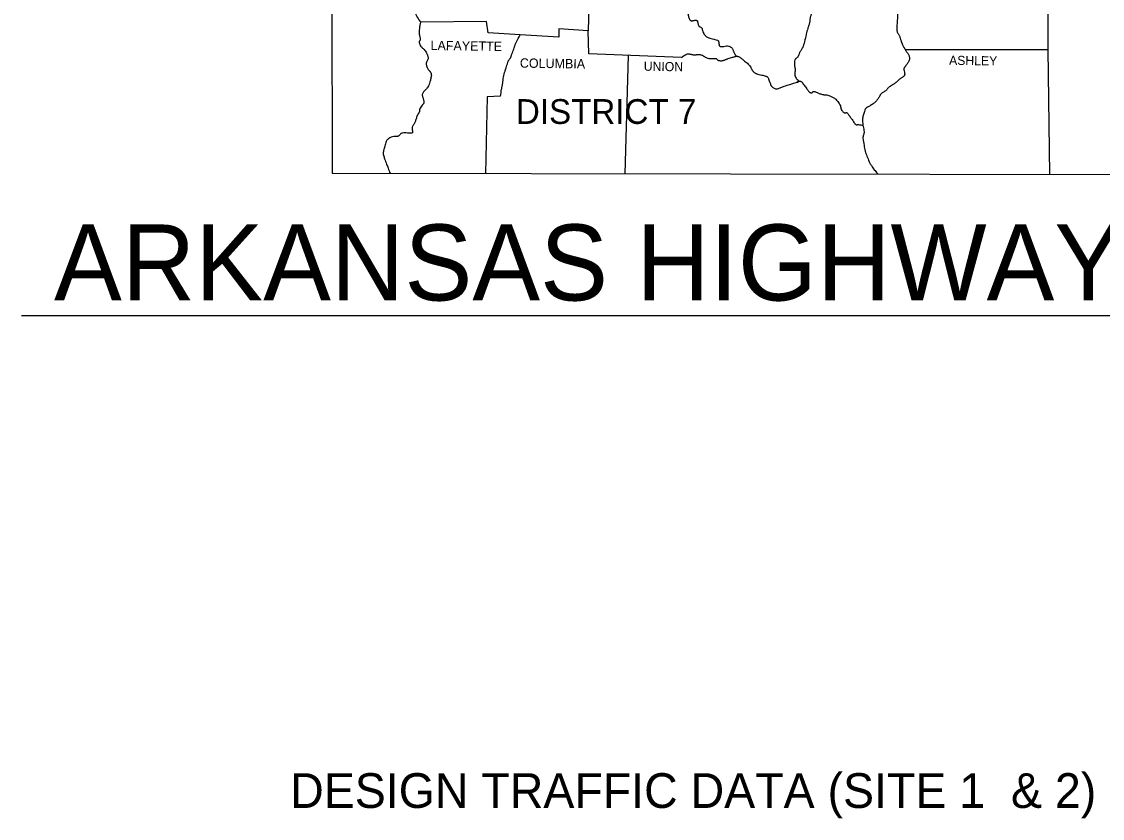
# Model space of a CAD drawing. Extents: x 982240 to 1103002, y 974866 to 1054902.
# Drawn here: x 1074271 to 1092173, y 1018146 to 1031353 of the extents above; entities that cross this region are included whole.
import ezdxf

# ---------------------------------------------------------------- set-up
doc = ezdxf.new("R2010")
doc.units = 0
for name, color, linetype in [('1', 7, 'Continuous'), ('Default', 7, 'Continuous'), ('R_Draft', 7, 'Continuous')]:
    doc.layers.add(name, color=color, linetype=linetype)

msp = doc.modelspace()

# ---------------------------------------------------------------- linework, layer by layer
at = {"layer": '1'}
for points in [[(1083703.9886225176, 1033012.2155825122), (1083657.1882101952, 1031197.8140686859), (1083171.2003717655, 1031230.2153271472), (1083167.6022496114, 1031097.0161299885), (1082527.014240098, 1031134.486481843)], [(1079409.2953796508, 1031752.2158338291), (1079416.4957613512, 1028839.815346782), (1092610.1656993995, 1028818.2158870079)], [(1082202.8269544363, 1030117.8162543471), (1081979.633050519, 1030103.4147755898), (1081955.1853419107, 1028835.6592383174)]]:
    msp.add_lwpolyline(points, dxfattribs=at)
for points in [[(1088790.6604119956, 1031590.2150583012), (1088779.8605290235, 1031478.6167001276), (1088776.262406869, 1031374.2149437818), (1088769.062025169, 1031273.4156258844), (1088767.087688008, 1031235.598910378), (1088767.3086761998, 1031216.6788174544), (1088769.062025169, 1031197.8140686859), (1088776.3027183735, 1031175.9372869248), (1088788.6335206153, 1031155.826065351), (1088801.9781133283, 1031136.0093056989), (1088812.2601779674, 1031115.0159096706), (1088837.460824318, 1031035.8146723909), (1088862.6587124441, 1030967.4152337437), (1088913.057246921, 1030877.4149561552), (1088924.268078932, 1030860.1013374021), (1088936.3278564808, 1030843.3429775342), (1088948.452087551, 1030826.5207473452), (1088959.856280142, 1030809.0155175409), (1088978.20725155, 1030760.7480627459), (1088979.756917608, 1030735.4033469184), (1088974.2556643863, 1030711.8145005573), (1088945.456895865, 1030661.416220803), (1088932.2416150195, 1030642.1728181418), (1088918.3002111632, 1030623.467603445), (1088904.4376407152, 1030604.8363081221), (1088891.4588600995, 1030585.8146636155), (1088885.4354231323, 1030552.9560086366), (1088893.1671679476, 1030515.3248719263), (1088899.144538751, 1030478.7389117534), (1088887.8579796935, 1030449.0157863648), (1088880.4175503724, 1030442.534947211), (1088872.4781238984, 1030436.8046951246), (1088855.7234263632, 1030426.7123790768), (1088838.8361810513, 1030416.9716919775), (1088823.058681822, 1030405.8154876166), (1088782.3237426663, 1030369.1105232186), (1088761.7694198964, 1030350.8515356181), (1088740.263256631, 1030333.8149896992), (1088693.462844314, 1030301.4164896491), (1088643.0629306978, 1030269.0152311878), (1088628.209558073, 1030256.1569261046), (1088615.1921282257, 1030241.1440818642), (1088602.6109354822, 1030225.6667126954), (1088589.0662740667, 1030211.4148328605), (1088569.875078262, 1030197.3160944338), (1088548.885977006, 1030185.1937644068), (1088528.1873537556, 1030172.6821338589), (1088509.8675919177, 1030157.4154938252), (1088493.7586899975, 1030136.2800200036), (1088480.4299675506, 1030112.9866138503), (1088467.4203282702, 1030089.4075782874), (1088452.268675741, 1030067.4152162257), (1088437.2962431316, 1030049.1207778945), (1088421.9703154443, 1030031.0722164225), (1088387.472136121, 1029999.0157776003), (1088333.4727212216, 1029963.0162182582), (1088314.6071453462, 1029951.5304510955), (1088295.4595497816, 1029940.6236635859), (1088267.060646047, 1029922.9799151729), (1088257.8749194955, 1029916.2148602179), (1088244.760818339, 1029901.5250716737), (1088236.335066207, 1029883.6092032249), (1088225.4738914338, 1029844.2157415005), (1088215.9339433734, 1029811.0186515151), (1088207.2961186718, 1029777.822225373), (1088201.4477083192, 1029744.5220684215), (1088200.2760033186, 1029711.0137859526), (1088204.660387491, 1029662.3356520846), (1088211.0745071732, 1029613.8141481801), (1088225.4738914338, 1029527.4163090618), (1088223.8529542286, 1029500.4159582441), (1088216.4710250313, 1029473.4156030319), (1088209.0908076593, 1029446.4152417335), (1088207.4750059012, 1029419.4148726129), (1088225.4738914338, 1029300.6157750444), (1088243.4741561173, 1029207.0158173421), (1088272.27430374, 1029124.2148999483), (1088311.8729552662, 1029030.6149422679), (1088335.361595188, 1028986.5048094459), (1088362.271489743, 1028944.2157239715), (1088407.4023034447, 1028882.752133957), (1088457.0853385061, 1028825.0149272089)], [(1082202.8269544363, 1030117.8162543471), (1082220.8258399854, 1030233.0142926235), (1082224.8831083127, 1030255.5947035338), (1082229.6028539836, 1030278.0579729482), (1082234.4338140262, 1030300.4998164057), (1082238.8247255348, 1030323.0159494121), (1082241.9532498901, 1030344.5411934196), (1082244.285017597, 1030366.1908963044), (1082246.586610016, 1030387.8529303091), (1082249.6246085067, 1030409.4151677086), (1082271.2243744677, 1030506.6148055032), (1082303.6226442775, 1030611.0151826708), (1082332.42141281, 1030697.4157801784), (1082336.1170022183, 1030705.6860105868), (1082340.8591860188, 1030713.4366187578), (1082352.1070546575, 1030728.063801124), (1082363.412454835, 1030742.6669926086), (1082368.2265529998, 1030750.3876122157), (1082372.0228225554, 1030758.6158585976), (1082378.443854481, 1030776.569236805), (1082384.6054780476, 1030794.620012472), (1082390.7755906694, 1030812.6684908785), (1082397.2220897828, 1030830.614977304), (1082429.6203596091, 1030917.0141956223), (1082437.343510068, 1030939.6851333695), (1082444.5642169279, 1030962.5647586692), (1082452.4125625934, 1030985.1691718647), (1082462.0186294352, 1031007.0144732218), (1082527.014240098, 1031134.486481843)]]:
    msp.add_spline(points, degree=3, dxfattribs=at)
at = {"layer": 'Default'}
for points in [[(1091267.398637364, 1033041.0157816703), (1091267.398637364, 1030888.2153756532), (1091296.1674780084, 1028820.367043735)], [(1081972.4312561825, 1031352.6146001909), (1080881.6582792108, 1031341.816443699)], [(1082527.014240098, 1031134.486481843), (1081997.6319360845, 1031165.4155686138), (1081972.4312561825, 1031352.6146001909)], [(1085201.550789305, 1030758.6158585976), (1083664.3885918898, 1030816.2134985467), (1083657.1882101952, 1031197.8140686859)], [(1088904.08492986, 1030891.8164349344), (1091267.398637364, 1030891.8164349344)], [(1084319.802163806, 1030791.6550784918), (1084262.6877868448, 1028831.8816080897)]]:
    msp.add_lwpolyline(points, dxfattribs=at)
for points in [[(1086089.3570193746, 1033160.2572362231), (1086087.0930818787, 1033048.3679949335), (1086084.5763867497, 1032992.4631158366), (1086082.5758888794, 1032964.5306763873), (1086079.9297788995, 1032936.6154044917), (1086069.0350314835, 1032880.494478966), (1086054.729132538, 1032825.0142879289), (1086045.1444954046, 1032773.9552819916), (1086039.0679090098, 1032748.7199653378), (1086034.8541442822, 1032736.3511370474), (1086032.3465934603, 1032730.2508408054), (1086029.5312444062, 1032724.2149700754), (1086018.6052799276, 1032707.5872354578), (1086004.951771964, 1032693.3169697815), (1085975.5318295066, 1032666.6145717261), (1085946.662048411, 1032637.8900108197), (1085917.9342924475, 1032609.0155525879), (1085863.934877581, 1032544.2157940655), (1085851.448016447, 1032524.9576722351), (1085840.6121293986, 1032504.617155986), (1085829.7378581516, 1032484.2756494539), (1085817.1358443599, 1032465.0145567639), (1085770.336811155, 1032414.6162770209), (1085709.1383937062, 1032364.2152388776), (1085647.9399762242, 1032328.2156795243), (1085579.5425561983, 1032295.814421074), (1085561.195891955, 1032289.9795412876), (1085542.1453718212, 1032286.3854944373), (1085522.8936486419, 1032283.0059659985), (1085503.9433753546, 1032277.814641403), (1085474.0414817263, 1032262.6909170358), (1085461.1371363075, 1032251.8515358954), (1085455.3108499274, 1032245.4117383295), (1085449.9453395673, 1032238.2154019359), (1085440.3468457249, 1032217.348654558), (1085437.283705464, 1032194.9831760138), (1085446.3444591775, 1032151.8161836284), (1085461.0037404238, 1032121.2008341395), (1085477.1031549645, 1032090.909350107), (1085493.122826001, 1032060.4708988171), (1085507.5428766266, 1032029.4146475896), (1085529.1412634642, 1031971.8142492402), (1085533.8913903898, 1031955.0859423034), (1085536.923410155, 1031937.8225876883), (1085537.8647968, 1031920.4552042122), (1085536.343024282, 1031903.4148106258), (1085511.1423779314, 1031863.8155711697), (1085453.5434617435, 1031831.4156919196), (1085385.1460416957, 1031791.8150732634), (1085323.9476242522, 1031755.8141347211), (1085309.4164316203, 1031744.2356686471), (1085297.7012587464, 1031729.5210616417), (1085288.309730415, 1031712.6533163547), (1085280.7494714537, 1031694.6154354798), (1085271.0732564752, 1031653.0734836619), (1085273.5504688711, 1031611.8158972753), (1085280.127384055, 1031587.4846301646), (1085287.8788003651, 1031563.2450397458), (1085295.6657430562, 1031538.9906238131), (1085302.349237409, 1031514.6148802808), (1085307.7414296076, 1031485.9254330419), (1085313.1477412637, 1031457.0158611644), (1085326.9032282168, 1031406.0561075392), (1085339.6173024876, 1031383.6989095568), (1085348.6555273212, 1031374.4791809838), (1085353.9976997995, 1031370.5063093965), (1085359.9467744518, 1031367.0142043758), (1085368.9107389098, 1031364.9493605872), (1085377.9097591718, 1031366.4270634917), (1085386.927074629, 1031369.0986016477), (1085395.9459246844, 1031370.615263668), (1085404.0450069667, 1031371.196860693), (1085412.1654191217, 1031372.366847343), (1085428.4280475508, 1031374.7056505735), (1085444.6494390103, 1031374.0989955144), (1085452.7183049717, 1031371.587159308), (1085456.737666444, 1031369.5859207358), (1085460.745222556, 1031367.0142043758), (1085466.2023319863, 1031358.6699789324), (1085467.944225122, 1031349.0158038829), (1085471.5437264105, 1031331.0146450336), (1085485.9431106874, 1031284.2160453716), (1085496.6047337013, 1031272.0990355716), (1085512.7640828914, 1031264.2394117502), (1085529.012799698, 1031256.4682948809), (1085539.9425255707, 1031244.6168059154), (1085542.464659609, 1031235.8855573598), (1085543.7222154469, 1031226.7115910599), (1085544.8896769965, 1031217.4896527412), (1085547.1415281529, 1031208.6144881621), (1085560.8473903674, 1031173.666687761), (1085579.5425561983, 1031140.2136703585), (1085590.9990375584, 1031125.6347414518), (1085603.6826554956, 1031112.7051174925), (1085633.5392128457, 1031093.4150706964), (1085673.1392434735, 1031079.0149711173), (1085755.9360477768, 1031053.8158312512), (1085799.1355796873, 1031043.0140325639), (1085805.265972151, 1031040.1450921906), (1085816.5658975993, 1031022.6435644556), (1085822.1280387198, 1030987.8404038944), (1085827.893708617, 1030954.5243081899), (1085834.6252748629, 1030943.3988337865), (1085845.934612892, 1030938.6150345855), (1085874.7287367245, 1030938.9673308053), (1085903.5321499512, 1030942.2160938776), (1085946.731681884, 1030949.4154540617), (1085983.1480196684, 1030947.6626796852), (1086001.0901162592, 1030941.6752567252), (1086009.9536803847, 1030937.120023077), (1086018.7299822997, 1030931.4156743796), (1086038.0069189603, 1030911.2204590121), (1086051.1296312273, 1030888.2153756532), (1086059.7452310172, 1030870.409527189), (1086067.2305704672, 1030852.2583363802), (1086074.7650077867, 1030834.0851958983), (1086083.5279010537, 1030816.2134985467), (1086102.52851999, 1030788.791992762), (1086112.724953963, 1030777.9937516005)], [(1087278.7002400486, 1032637.8157517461), (1087281.4197511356, 1032581.961295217), (1087284.8591124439, 1032526.1425324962), (1087293.0982452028, 1032414.6162770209), (1087299.4612541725, 1032387.1836858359), (1087310.5614141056, 1032360.5555213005), (1087321.0295570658, 1032333.9573754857), (1087324.3487571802, 1032320.4275571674), (1087325.496515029, 1032306.6148405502), (1087323.8233847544, 1032277.8893810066), (1087320.4667697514, 1032249.117829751), (1087316.9254014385, 1032220.2949295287), (1087314.6980111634, 1032191.4154230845), (1087311.0971307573, 1032079.8143065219), (1087311.0971307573, 1031979.0149886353), (1087311.0971307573, 1031881.8153508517), (1087311.0971307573, 1031781.0160329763), (1087318.2975124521, 1031709.0155350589), (1087323.643913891, 1031682.6927331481), (1087330.3689179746, 1031656.7232690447), (1087337.3580361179, 1031630.8001884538), (1087343.4967797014, 1031604.6165370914), (1087352.241520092, 1031556.0075339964), (1087354.5482273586, 1031531.6144112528), (1087354.298041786, 1031507.4155201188), (1087350.6389979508, 1031483.9216817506), (1087344.5315407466, 1031460.5763938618), (1087337.9067029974, 1031437.2506796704), (1087332.6955175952, 1031413.8155624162), (1087330.0225062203, 1031392.2812578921), (1087328.1671782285, 1031370.5216301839), (1087325.8767387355, 1031348.8088192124), (1087321.898392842, 1031327.4149649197), (1087315.4223878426, 1031305.5962119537), (1087307.7097639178, 1031284.1470273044), (1087299.8914175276, 1031262.7316620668), (1087293.0982452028, 1031241.0143674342), (1087267.8989779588, 1031143.8147296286), (1087239.0988303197, 1031017.8162718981), (1087227.9642930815, 1030976.0040740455), (1087221.357988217, 1030955.3897647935), (1087213.8995630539, 1030935.0153545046), (1087203.004972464, 1030912.4920665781), (1087189.805584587, 1030891.1481191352), (1087176.053552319, 1030870.1376399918), (1087163.501028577, 1030848.614756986), (1087154.706967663, 1030829.1822176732), (1087147.0760617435, 1030809.0674575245), (1087139.5580717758, 1030788.9263826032), (1087131.1027587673, 1030769.4148988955), (1087119.9919581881, 1030755.9525380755), (1087104.9990664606, 1030745.1235227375), (1087090.458042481, 1030733.8399359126), (1087084.7113430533, 1030727.0627041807), (1087080.702845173, 1030719.0138607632), (1087072.6862148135, 1030675.8338702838), (1087073.5038425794, 1030632.6160216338), (1087075.822927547, 1030612.8162357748), (1087079.0791519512, 1030593.0184359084), (1087082.2476923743, 1030573.2191195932), (1087084.3037255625, 1030553.4147843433), (1087083.599700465, 1030535.4516362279), (1087080.7780070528, 1030517.4437576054), (1087077.9194222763, 1030499.4216126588), (1087077.1047230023, 1030481.4156656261), (1087083.5707103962, 1030446.5703857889), (1087102.3026111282, 1030413.0162270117), (1087114.2948202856, 1030398.3160454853), (1087127.2178585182, 1030384.4152191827), (1087153.6203749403, 1030366.3540719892)], [(1079409.2953796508, 1031752.2158338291), (1079535.293094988, 1031806.2151728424), (1079589.292509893, 1031788.2140139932), (1079636.0915430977, 1031741.415414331), (1079690.0881997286, 1031741.415414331), (1079718.8897265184, 1031784.6143338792), (1079772.8863831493, 1031788.2140139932), (1079816.084535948, 1031784.6143338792), (1079862.8849482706, 1031813.4159122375), (1079902.483599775, 1031831.4156919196), (1079956.4830146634, 1031849.4154715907), (1079996.0830452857, 1031863.8155711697), (1080032.080816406, 1031903.4148106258), (1080096.8787351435, 1031935.8160690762), (1080172.476536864, 1031961.0152089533), (1080194.0763028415, 1031997.0161475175), (1080230.075453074, 1032011.4148679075), (1080302.0737535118, 1032007.8151878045), (1080348.8727866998, 1032029.4146475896), (1080388.4714382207, 1032011.4148679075), (1080424.4705884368, 1031986.2143488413), (1080431.6695910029, 1031892.6157703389), (1080460.469738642, 1031842.2161113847), (1080503.6692705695, 1031752.2158338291), (1080564.866308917, 1031705.4158549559), (1080622.4652250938, 1031658.6144969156), (1080644.0649910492, 1031629.8142977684), (1080705.264787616, 1031575.8163379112), (1080759.2628233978, 1031557.815179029), (1080784.462090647, 1031518.2159395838), (1080824.0607421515, 1031424.6146027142), (1080881.6582792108, 1031341.816443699)], [(1080881.6582792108, 1031341.816443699), (1080869.16222442, 1031295.5715398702), (1080864.1421879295, 1031265.9448360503), (1080860.0598923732, 1031237.4146873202), (1080856.4603911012, 1031154.6165283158), (1080859.1191552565, 1031130.0264634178), (1080864.8569138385, 1031105.5223518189), (1080870.8961324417, 1031081.2650742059), (1080874.45927665, 1031057.4155113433), (1080871.7854040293, 1031045.5602665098), (1080865.1192862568, 1031033.8682798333), (1080858.6234423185, 1031022.2499142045), (1080856.4603911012, 1031010.6155325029), (1080859.8341387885, 1030993.3485512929), (1080865.7983458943, 1030976.1464538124), (1080885.259159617, 1030942.2160938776), (1080898.4861488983, 1030926.8804918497), (1080912.496105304, 1030914.0441091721), (1080926.3870978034, 1030901.7935392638), (1080939.2571953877, 1030888.2153756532), (1080960.0711326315, 1030860.859052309), (1080978.8558468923, 1030830.614977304), (1080988.6136648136, 1030810.0164726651), (1080995.8224456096, 1030789.2249992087), (1081000.8480886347, 1030768.4282854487), (1081004.0564932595, 1030747.8140599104), (1081000.0120153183, 1030724.4040913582), (1080987.7998276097, 1030701.0022088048), (1080975.6160604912, 1030677.6066071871), (1080971.6568443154, 1030654.215481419), (1080976.2840854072, 1030629.7844752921), (1080983.976826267, 1030605.4431218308), (1081007.6559945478, 1030557.0144644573), (1081015.3010622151, 1030547.1667525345), (1081024.0242997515, 1030539.0305650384), (1081032.663296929, 1030530.8864373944), (1081040.055643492, 1030521.0149051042), (1081058.054529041, 1030463.4158859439), (1081054.5851127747, 1030435.5488259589), (1081048.8502574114, 1030407.6001492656), (1081032.8552617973, 1030351.8147693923), (1081000.4556128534, 1030269.0152311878), (1080993.0656228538, 1030257.4169023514), (1080984.6642717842, 1030246.7101034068), (1080965.9304227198, 1030226.9013991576), (1080946.4599383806, 1030207.4497263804), (1080928.4586915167, 1030186.2156929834), (1080906.858925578, 1030146.6164535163), (1080917.657429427, 1030092.6143561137), (1080922.85634906, 1030070.9497782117), (1080928.61462146, 1030049.263900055), (1080933.3943640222, 1030027.6534453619), (1080934.9366982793, 1030016.9067279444), (1080935.4118782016, 1030011.5532863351), (1080935.6576941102, 1030006.2151378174), (1080929.06104324, 1029992.9894681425), (1080923.1090814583, 1029987.0544296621), (1080917.657429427, 1029981.0159979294), (1080894.017931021, 1029950.5894248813), (1080870.8597753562, 1029919.815919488), (1080864.3077642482, 1029903.9990238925), (1080862.2108510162, 1029886.3117199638), (1080860.8385538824, 1029868.2766561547), (1080856.4603911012, 1029851.4164808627), (1080848.7946886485, 1029836.8733062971), (1080840.0547281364, 1029822.7403658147), (1080831.4176868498, 1029808.54538331), (1080824.0607421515, 1029793.8160825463), (1080814.40426392, 1029768.0222917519), (1080805.8783179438, 1029741.6545486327), (1080797.4437965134, 1029715.2678229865), (1080788.0615919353, 1029689.4170845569), (1080777.5779044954, 1029667.2887068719), (1080765.2834194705, 1029645.8068912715), (1080752.6786071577, 1029624.5296781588), (1080741.2639378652, 1029603.015107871), (1080738.949742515, 1029575.6754174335), (1080744.7285003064, 1029543.6132916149), (1080746.97488143, 1029516.9521644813), (1080743.1405152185, 1029508.8105485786), (1080734.0635561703, 1029505.8154700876), (1080662.0652557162, 1029505.8154700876), (1080579.2670722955, 1029505.8154700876), (1080558.525454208, 1029498.410675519), (1080540.881819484, 1029481.5692913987), (1080523.531360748, 1029463.3508170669), (1080503.6692705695, 1029451.8147518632), (1080486.9661136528, 1029449.6827573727), (1080469.68638789, 1029449.8905766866), (1080452.2984036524, 1029450.1605635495), (1080435.2704714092, 1029448.2150717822), (1080392.798001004, 1029436.7750452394), (1080352.4736671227, 1029415.8151925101), (1080335.2331943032, 1029401.2031360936), (1080320.9510237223, 1029384.9756305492), (1080302.0737535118, 1029347.4157538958), (1080284.0734888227, 1029271.8155758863), (1080278.6156161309, 1029253.8163023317), (1080272.5321265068, 1029235.8563274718), (1080262.475101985, 1029199.816457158), (1080260.720339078, 1029169.3134255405), (1080265.0992802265, 1029138.2353755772), (1080273.5657289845, 1029107.3474823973), (1080284.0734888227, 1029077.4149211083), (1080316.47451689, 1028991.0157028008), (1080341.6724050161, 1028922.6148849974), (1080373.9269056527, 1028838.2479288)], [(1085201.550789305, 1030758.6158585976), (1085259.1510845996, 1030798.2150980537), (1085313.1477412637, 1030819.8145578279), (1085340.03427056, 1030815.1307399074), (1085353.547070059, 1030811.7301533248), (1085367.1471561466, 1030809.0155175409), (1085424.7446932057, 1030801.8161573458), (1085437.3487096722, 1030802.392792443), (1085449.9485072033, 1030804.8880751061), (1085462.5463761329, 1030807.647238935), (1085475.1446068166, 1030809.0155175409), (1085539.9425255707, 1030798.2150980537), (1085554.401131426, 1030790.8694859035), (1085567.5720320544, 1030782.3500040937), (1085580.428033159, 1030773.6634442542), (1085593.941940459, 1030765.8165979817), (1085623.7130027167, 1030749.4891099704), (1085655.140357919, 1030740.6146997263), (1085716.3373962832, 1030740.6146997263), (1085770.336811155, 1030740.6146997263), (1085783.1218133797, 1030736.0392453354), (1085794.1004615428, 1030725.7136130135), (1085804.8970428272, 1030714.738899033), (1085817.1358443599, 1030708.2161996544), (1085838.3687433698, 1030705.2159836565), (1085860.4451941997, 1030704.4598541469), (1085882.466046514, 1030706.4814726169), (1085903.5321499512, 1030711.8145005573), (1085921.571055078, 1030718.7784393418), (1085939.4410952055, 1030726.3581411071), (1085957.3565825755, 1030733.8660723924), (1085975.5318295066, 1030740.6146997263), (1086047.5301299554, 1030762.2155386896), (1086071.7703347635, 1030769.4641795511), (1086096.728032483, 1030775.8901230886), (1086121.3858260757, 1030778.1788793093), (1086133.2843222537, 1030776.7360340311), (1086144.726318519, 1030773.0159581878), (1086189.5769739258, 1030745.3082683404), (1086231.1253823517, 1030711.8145005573), (1086262.1223687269, 1030687.0709096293), (1086292.322420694, 1030661.416220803), (1086342.723713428, 1030603.8158224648), (1086352.5509013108, 1030588.2210404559), (1086360.7141928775, 1030571.6033497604), (1086368.8816875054, 1030554.8919558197), (1086378.7214845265, 1030539.0160639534), (1086418.3215151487, 1030503.0151253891), (1086434.0979483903, 1030495.0028691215), (1086450.1019718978, 1030488.1754928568), (1086483.1180547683, 1030477.815985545), (1086533.5179683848, 1030467.0155660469), (1086594.715006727, 1030449.0157863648), (1086612.123776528, 1030444.1707072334), (1086620.2288041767, 1030440.5039001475), (1086627.1160347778, 1030434.6156867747), (1086637.3104472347, 1030418.4389540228), (1086643.9881801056, 1030401.15509807), (1086649.429187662, 1030383.5013320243), (1086655.9134241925, 1030366.2148689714), (1086660.8571391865, 1030354.3438050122), (1086665.0685506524, 1030342.5052597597), (1086673.2769767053, 1030318.9585402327), (1086684.5037295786, 1030295.6403404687), (1086692.4880495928, 1030284.0874448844), (1086697.2897829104, 1030278.3411372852), (1086702.7138365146, 1030272.616290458), (1086724.4306630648, 1030254.626367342), (1086747.0797333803, 1030242.8346808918), (1086770.0454965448, 1030237.8334845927), (1086792.7124016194, 1030240.2150320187), (1086820.5569911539, 1030249.8330632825), (1086848.3507179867, 1030261.6186701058), (1086876.2245246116, 1030273.5025326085), (1086904.309353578, 1030283.4153307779), (1086994.3051604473, 1030308.6158498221), (1087059.1044583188, 1030330.2153096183), (1087098.7031098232, 1030344.6167883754), (1087107.5153076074, 1030346.3463020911), (1087116.6998115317, 1030346.5538729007), (1087125.8857521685, 1030346.6924766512), (1087134.7022600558, 1030348.2150893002), (1087135.2605830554, 1030348.8163829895), (1087134.2304529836, 1030349.6146526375), (1087129.4911793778, 1030351.578909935), (1087124.6571305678, 1030353.6614417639), (1087123.5085315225, 1030354.6075545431), (1087123.900997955, 1030355.4158286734), (1087134.0779537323, 1030360.3319526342), (1087145.4678505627, 1030364.4805531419), (1087167.101909, 1030366.2148689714), (1087177.595782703, 1030362.1467343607), (1087188.226816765, 1030355.589619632), (1087206.7005604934, 1030337.4160489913), (1087213.3746726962, 1030327.5085919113), (1087219.4011134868, 1030317.4467092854), (1087225.377094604, 1030307.4689970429), (1087231.899827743, 1030297.8140511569), (1087275.0979805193, 1030240.2150320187), (1087293.9497314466, 1030214.8719229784), (1087303.8193433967, 1030202.3277404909), (1087314.6980111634, 1030189.8153730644), (1087323.496199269, 1030182.4903084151), (1087333.613423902, 1030177.2718448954), (1087344.1729498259, 1030173.8252005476), (1087354.298041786, 1030171.8155933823), (1087364.1358633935, 1030174.9640055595), (1087373.8613209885, 1030183.4657902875), (1087383.7044570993, 1030191.5423415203), (1087393.8953141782, 1030193.4150531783), (1087447.8947290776, 1030175.4166526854), (1087494.6937622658, 1030157.4154938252), (1087548.6917980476, 1030143.0153942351), (1087560.31910801, 1030141.540477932), (1087572.0495538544, 1030140.9575651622), (1087583.8005353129, 1030140.5036468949), (1087595.4894521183, 1030139.4157141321), (1087656.6892487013, 1030125.015614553), (1087703.4882818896, 1030099.8150954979), (1087746.6878138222, 1030074.6159556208), (1087789.8859666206, 1030027.8145975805), (1087833.085498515, 1029955.8154788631), (1087837.801427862, 1029941.9380408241), (1087840.3648414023, 1029927.3396996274), (1087842.8884295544, 1029912.5791484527), (1087847.4848827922, 1029898.2150805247), (1087868.8235745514, 1029866.0759875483), (1087882.6020526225, 1029852.6164113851), (1087897.8834172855, 1029840.6146821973), (1087909.3253373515, 1029838.4568165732), (1087922.5785224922, 1029841.7965812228), (1087935.1839133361, 1029844.5453963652), (1087944.6824504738, 1029840.6146821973), (1087962.1693122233, 1029817.4796595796), (1087979.3638132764, 1029794.1580497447), (1088013.0812496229, 1029747.0147245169), (1088038.2791377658, 1029711.0137859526), (1088061.6058832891, 1029676.3482993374), (1088075.151323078, 1029660.2629504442), (1088083.158132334, 1029652.927911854), (1088092.278552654, 1029646.2154066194), (1088101.791748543, 1029643.1960562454), (1088111.7922430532, 1029644.138860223), (1088121.9355552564, 1029646.1199373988), (1088131.8772041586, 1029646.2154066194), (1088208.6561692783, 1029631.5304053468)]]:
    msp.add_spline(points, degree=3, dxfattribs=at)
at = {"layer": 'R_Draft'}
msp.add_line((1074270.618475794, 1026481.8156660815), (1098074.6880656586, 1026481.8156660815), dxfattribs=at)

# ---------------------------------------------------------------- texts
at = {"layer": 'Default'}
for s, height, rotation, p in [('LAFAYETTE', 154.78103762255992, 359.18385390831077, (1081043.6565238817, 1030881.0146362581)), ('COLUMBIA', 154.78341269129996, 359.2124581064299, (1082523.2184260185, 1030589.4157229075)), ('UNION', 151.21941390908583, 358.958345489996, (1084575.1658512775, 1030539.0160639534)), ('ASHLEY', 151.21941505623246, 359.2360842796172, (1089633.0388722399, 1030636.215701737))]:
    msp.add_text(s, height=height, rotation=rotation, dxfattribs=at).set_placement(p)
msp.add_text('DISTRICT 7', height=410.3954235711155, dxfattribs=at).set_placement((1082458.4205072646, 1029657.0158261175))
at = {"layer": 'R_Draft'}
for s, height, p in [('ARKANSAS HIGHWAY DISTRICT 6', 1259.9999999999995, (1074807.1316934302, 1026730.2084663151)), ('DESIGN TRAFFIC DATA (SITE 1  & 2)', 575.9999999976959, (1078719.4724953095, 1018319.4481843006))]:
    msp.add_text(s, height=height, dxfattribs=at).set_placement(p)

doc.saveas('drawing.dxf')
